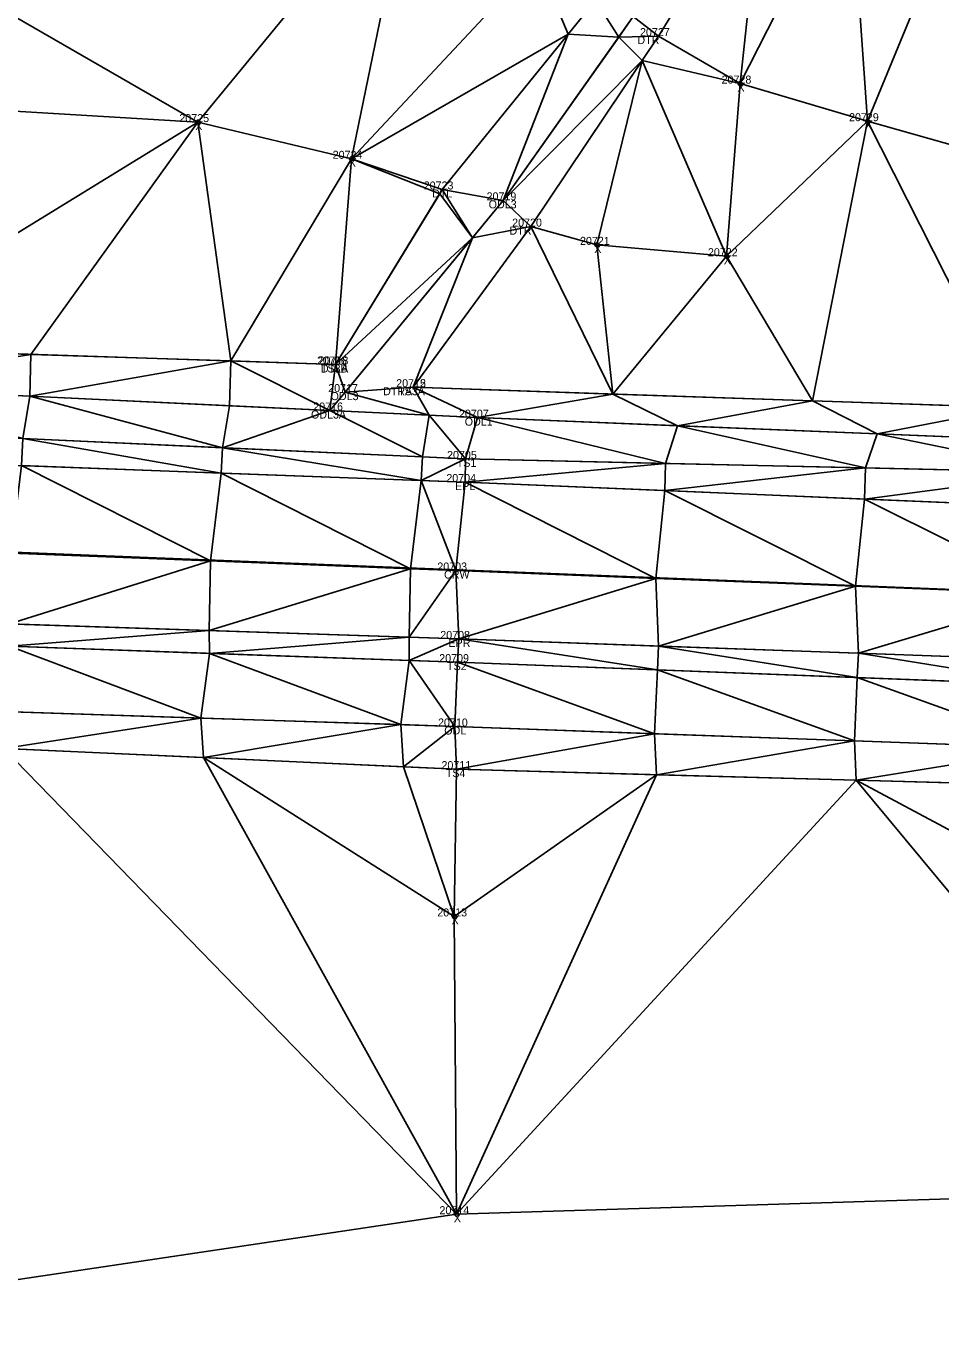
# Model space of a CAD drawing. Extents: x 1966740 to 1969291, y 1117379 to 1118460.
# Drawn here: x 1968833.8 to 1968948.1, y 1117803.8 to 1117968.4 of the extents above; entities that cross this region are included whole.
import ezdxf

# ---------------------------------------------------------------- set-up
doc = ezdxf.new("R2010")
doc.units = 0
for name, color, linetype in [('Level 1', 7, 'Continuous'), ('Level 10', 7, 'Continuous'), ('Level 3', 7, 'Continuous'), ('Level 30', 7, 'Continuous'), ('Level 35', 7, 'Continuous'), ('Level 50', 7, 'Continuous'), ('Level 52', 7, 'Continuous'), ('Level 53', 7, 'Continuous'), ('Level 56', 7, 'Continuous'), ('Level 6', 7, 'Continuous'), ('Level 60', 7, 'Continuous'), ('Level 61', 7, 'Continuous'), ('Level 62', 7, 'Continuous')]:
    doc.layers.add(name, color=color, linetype=linetype)

msp = doc.modelspace()

# ---------------------------------------------------------------- linework, layer by layer
at = {"layer": 'Level 1'}
msp.add_line((1968120.33, 1117930.94), (1969279.02, 1117884.95), dxfattribs=at)
at = {"layer": 'Level 10'}
for points in [[(1968872.44, 1117926.13), (1968885.78, 1117948), (1968904.93, 1117971.61), (1968923.41, 1117996.78), (1968940.56, 1118022.16)], [(1968882.13, 1117923.29), (1968896.84, 1117943.36), (1968912.83, 1117967.16), (1968928.85, 1117993.17), (1968947.1, 1118017.99)]]:
    msp.add_lwpolyline(points, dxfattribs=at)
at = {"layer": 'Level 3'}
for points in [[(1968532.27, 1117940.77), (1968682.68, 1117932.75), (1968784.38, 1117929.07), (1968872.44, 1117926.13)], [(1968531.49, 1117931.42), (1968682.06, 1117924.3), (1968783.42, 1117919.17), (1968888.7, 1117914.33), (1968991.06, 1117912.02), (1969093.07, 1117907.16), (1969191.83, 1117902.92), (1969283.72, 1117899.63)], [(1968530.54, 1117925.7), (1968681.97, 1117919.01), (1968783.23, 1117915.36), (1968888.64, 1117911.44), (1968991.22, 1117907.09), (1969091.98, 1117903.06), (1969191.09, 1117898.66), (1969283.27, 1117895.43)], [(1968882.13, 1117923.29), (1968991.72, 1117919.56), (1969094.35, 1117914.97), (1969192.08, 1117910.66), (1969282.99, 1117908.48)], [(1968529.36, 1117916.3), (1968681.48, 1117908.5), (1968781.89, 1117904.51), (1968887.49, 1117900.39), (1968989.06, 1117896.4), (1969090.87, 1117891.24), (1969190.23, 1117887.94), (1969284.4, 1117884.73)], [(1968527.82, 1117906.41), (1968680.79, 1117899.07), (1968781.71, 1117895.37), (1968887.86, 1117891.84), (1968988.65, 1117888.23), (1969090.1, 1117882.83), (1969189.3, 1117879.04), (1969282.94, 1117875.42)], [(1968528.99, 1117899.6), (1968680.45, 1117894.84), (1968781.74, 1117892.71), (1968887.7, 1117888.94), (1968987.81, 1117885.08), (1969089.75, 1117880.01), (1969189.02, 1117876.39), (1969282.76, 1117873.05)], [(1968528.68, 1117880.51), (1968680.3, 1117884.55), (1968781.05, 1117880.46), (1968887.57, 1117875.57), (1968986, 1117872.85), (1969087.95, 1117867.56), (1969189.32, 1117864.4), (1969289.73, 1117862.33)]]:
    msp.add_lwpolyline(points, dxfattribs=at)
at = {"layer": 'Level 30'}
for centre in [(1968923.03, 1117961.23), (1968855.24, 1117956.42), (1968938.93, 1117956.53), (1968874.43, 1117951.83), (1968905.11, 1117941.08), (1968921.32, 1117939.66), (1968887.28, 1117857.17), (1968887.56, 1117819.96)]:
    msp.add_circle(centre, 0.25, dxfattribs=at)
at = {"layer": 'Level 35'}
for points in [[(1968785.82, 1117960.59), (1968789.99, 1117994), (1968855.24, 1117956.42)], [(1968789.99, 1117994), (1968882.12, 1117989.12), (1968855.24, 1117956.42)], [(1968855.24, 1117956.42), (1968882.12, 1117989.12), (1968874.43, 1117951.83)], [(1968874.43, 1117951.83), (1968882.12, 1117989.12), (1968897.65, 1117976.64)], [(1968909.65, 1117969.6), (1968925.94, 1117988.45), (1968912.83, 1117967.16)], [(1968912.83, 1117967.16), (1968925.94, 1117988.45), (1968923.03, 1117961.23)], [(1968923.03, 1117961.23), (1968925.94, 1117988.45), (1968936.75, 1117988.2)], [(1968923.03, 1117961.23), (1968936.75, 1117988.2), (1968938.93, 1117956.53)], [(1968936.75, 1117988.2), (1968949.07, 1117981.12), (1968938.93, 1117956.53)], [(1968938.93, 1117956.53), (1968949.07, 1117981.12), (1968995.87, 1117940.46)], [(1968874.43, 1117951.83), (1968897.65, 1117976.64), (1968901.53, 1117967.41)], [(1968897.65, 1117976.64), (1968904.93, 1117971.61), (1968901.53, 1117967.41)], [(1968901.53, 1117967.41), (1968904.93, 1117971.61), (1968907.84, 1117967.04)], [(1968904.93, 1117971.61), (1968909.65, 1117969.6), (1968907.84, 1117967.04)], [(1968907.84, 1117967.04), (1968909.65, 1117969.6), (1968912.83, 1117967.16)], [(1968874.43, 1117951.83), (1968901.53, 1117967.41), (1968885.78, 1117948)], [(1968885.78, 1117948), (1968901.53, 1117967.41), (1968893.41, 1117946.64)], [(1968893.41, 1117946.64), (1968901.53, 1117967.41), (1968907.84, 1117967.04)], [(1968893.41, 1117946.64), (1968907.84, 1117967.04), (1968910.78, 1117964.12)], [(1968907.84, 1117967.04), (1968912.83, 1117967.16), (1968910.78, 1117964.12)], [(1968910.78, 1117964.12), (1968912.83, 1117967.16), (1968923.03, 1117961.23)], [(1968893.41, 1117946.64), (1968910.78, 1117964.12), (1968896.84, 1117943.36)], [(1968896.84, 1117943.36), (1968910.78, 1117964.12), (1968905.11, 1117941.08)], [(1968905.11, 1117941.08), (1968910.78, 1117964.12), (1968921.32, 1117939.66)], [(1968910.78, 1117964.12), (1968923.03, 1117961.23), (1968921.32, 1117939.66)], [(1968921.32, 1117939.66), (1968923.03, 1117961.23), (1968938.93, 1117956.53)], [(1968785.82, 1117960.59), (1968855.24, 1117956.42), (1968809.36, 1117928.24)], [(1968809.36, 1117928.24), (1968855.24, 1117956.42), (1968834.35, 1117927.4)], [(1968834.35, 1117927.4), (1968855.24, 1117956.42), (1968859.33, 1117926.57)], [(1968855.24, 1117956.42), (1968874.43, 1117951.83), (1968859.33, 1117926.57)], [(1968921.32, 1117939.66), (1968938.93, 1117956.53), (1968932.08, 1117921.59)], [(1968932.08, 1117921.59), (1968938.93, 1117956.53), (1968957.06, 1117920.74)], [(1968938.93, 1117956.53), (1968995.87, 1117940.46), (1968957.06, 1117920.74)], [(1968859.33, 1117926.57), (1968874.43, 1117951.83), (1968872.44, 1117926.13)], [(1968872.44, 1117926.13), (1968874.43, 1117951.83), (1968885.46, 1117947.47)], [(1968874.43, 1117951.83), (1968885.78, 1117948), (1968885.46, 1117947.47)], [(1968885.46, 1117947.47), (1968885.78, 1117948), (1968889.55, 1117941.97)], [(1968885.78, 1117948), (1968893.41, 1117946.64), (1968889.55, 1117941.97)], [(1968872.44, 1117926.13), (1968885.46, 1117947.47), (1968889.55, 1117941.97)], [(1968889.55, 1117941.97), (1968893.41, 1117946.64), (1968896.84, 1117943.36)], [(1968882.13, 1117923.29), (1968889.55, 1117941.97), (1968896.84, 1117943.36)], [(1968882.13, 1117923.29), (1968896.84, 1117943.36), (1968907.11, 1117922.44)], [(1968896.84, 1117943.36), (1968905.11, 1117941.08), (1968907.11, 1117922.44)], [(1968872.44, 1117926.13), (1968889.55, 1117941.97), (1968873.64, 1117922.68)], [(1968873.64, 1117922.68), (1968889.55, 1117941.97), (1968882.13, 1117923.29)], [(1968905.11, 1117941.08), (1968921.32, 1117939.66), (1968907.11, 1117922.44)], [(1968907.11, 1117922.44), (1968921.32, 1117939.66), (1968932.08, 1117921.59)], [(1968809.25, 1117923.37), (1968809.36, 1117928.24), (1968834.35, 1117927.4)], [(1968809.25, 1117923.37), (1968834.35, 1117927.4), (1968834.22, 1117922.17)], [(1968834.22, 1117922.17), (1968834.35, 1117927.4), (1968859.33, 1117926.57)], [(1968834.22, 1117922.17), (1968859.33, 1117926.57), (1968859.19, 1117920.98)], [(1968859.19, 1117920.98), (1968859.33, 1117926.57), (1968871.74, 1117920.38)], [(1968859.33, 1117926.57), (1968872.44, 1117926.13), (1968871.74, 1117920.38)], [(1968871.74, 1117920.38), (1968872.44, 1117926.13), (1968873.64, 1117922.68)], [(1968809.25, 1117923.37), (1968834.22, 1117922.17), (1968833.35, 1117916.87)], [(1968873.64, 1117922.68), (1968882.13, 1117923.29), (1968884.15, 1117919.78)], [(1968882.13, 1117923.29), (1968907.11, 1117922.44), (1968890.2, 1117919.49)], [(1968882.13, 1117923.29), (1968890.2, 1117919.49), (1968884.15, 1117919.78)], [(1968833.35, 1117916.87), (1968834.22, 1117922.17), (1968858.32, 1117915.73)], [(1968834.22, 1117922.17), (1968859.19, 1117920.98), (1968858.32, 1117915.73)], [(1968871.74, 1117920.38), (1968873.64, 1117922.68), (1968884.15, 1117919.78)], [(1968890.2, 1117919.49), (1968907.11, 1117922.44), (1968915.17, 1117918.47)], [(1968907.11, 1117922.44), (1968932.08, 1117921.59), (1968915.17, 1117918.47)], [(1968858.32, 1117915.73), (1968859.19, 1117920.98), (1968871.74, 1117920.38)], [(1968858.32, 1117915.73), (1968871.74, 1117920.38), (1968883.29, 1117914.58)], [(1968871.74, 1117920.38), (1968884.15, 1117919.78), (1968883.29, 1117914.58)], [(1968915.17, 1117918.47), (1968932.08, 1117921.59), (1968940.14, 1117917.45)], [(1968932.08, 1117921.59), (1968957.06, 1117920.74), (1968940.14, 1117917.45)], [(1968940.14, 1117917.45), (1968957.06, 1117920.74), (1968965.12, 1117916.43)], [(1968883.29, 1117914.58), (1968884.15, 1117919.78), (1968888.7, 1117914.33)], [(1968884.15, 1117919.78), (1968890.2, 1117919.49), (1968888.7, 1117914.33)], [(1968888.7, 1117914.33), (1968890.2, 1117919.49), (1968913.69, 1117913.76)], [(1968890.2, 1117919.49), (1968915.17, 1117918.47), (1968913.69, 1117913.76)], [(1968913.69, 1117913.76), (1968915.17, 1117918.47), (1968938.68, 1117913.2)], [(1968915.17, 1117918.47), (1968940.14, 1117917.45), (1968938.68, 1117913.2)], [(1968833.18, 1117913.5), (1968833.35, 1117916.87), (1968858.16, 1117912.57)], [(1968833.35, 1117916.87), (1968858.32, 1117915.73), (1968858.16, 1117912.57)], [(1968938.68, 1117913.2), (1968940.14, 1117917.45), (1968963.67, 1117912.63)], [(1968940.14, 1117917.45), (1968965.12, 1117916.43), (1968963.67, 1117912.63)], [(1968858.16, 1117912.57), (1968858.32, 1117915.73), (1968883.14, 1117911.64)], [(1968858.32, 1117915.73), (1968883.29, 1117914.58), (1968883.14, 1117911.64)], [(1968831.84, 1117902.56), (1968833.18, 1117913.5), (1968856.81, 1117901.58)], [(1968833.18, 1117913.5), (1968858.16, 1117912.57), (1968856.81, 1117901.58)], [(1968883.14, 1117911.64), (1968883.29, 1117914.58), (1968888.7, 1117914.33)], [(1968883.14, 1117911.64), (1968888.7, 1117914.33), (1968888.64, 1117911.44)], [(1968888.64, 1117911.44), (1968888.7, 1117914.33), (1968913.69, 1117913.76)], [(1968888.64, 1117911.44), (1968913.69, 1117913.76), (1968913.61, 1117910.38)], [(1968913.61, 1117910.38), (1968913.69, 1117913.76), (1968938.68, 1117913.2)], [(1968856.81, 1117901.58), (1968858.16, 1117912.57), (1968881.79, 1117900.61)], [(1968858.16, 1117912.57), (1968883.14, 1117911.64), (1968881.79, 1117900.61)], [(1968913.61, 1117910.38), (1968938.68, 1117913.2), (1968938.58, 1117909.32)], [(1968938.58, 1117909.32), (1968938.68, 1117913.2), (1968963.67, 1117912.63)], [(1968938.58, 1117909.32), (1968963.67, 1117912.63), (1968963.55, 1117908.26)], [(1968881.79, 1117900.61), (1968883.14, 1117911.64), (1968887.49, 1117900.39)], [(1968883.14, 1117911.64), (1968888.64, 1117911.44), (1968887.49, 1117900.39)], [(1968887.49, 1117900.39), (1968888.64, 1117911.44), (1968912.46, 1117899.41)], [(1968888.64, 1117911.44), (1968913.61, 1117910.38), (1968912.46, 1117899.41)], [(1968912.46, 1117899.41), (1968913.61, 1117910.38), (1968937.44, 1117898.43)], [(1968913.61, 1117910.38), (1968938.58, 1117909.32), (1968937.44, 1117898.43)], [(1968937.44, 1117898.43), (1968938.58, 1117909.32), (1968962.41, 1117897.45)], [(1968938.58, 1117909.32), (1968963.55, 1117908.26), (1968962.41, 1117897.45)], [(1968831.67, 1117893.71), (1968831.84, 1117902.56), (1968856.81, 1117901.58)], [(1968831.67, 1117893.71), (1968856.81, 1117901.58), (1968856.65, 1117892.88)], [(1968856.65, 1117892.88), (1968856.81, 1117901.58), (1968881.79, 1117900.61)], [(1968856.65, 1117892.88), (1968881.79, 1117900.61), (1968881.64, 1117892.05)], [(1968881.64, 1117892.05), (1968881.79, 1117900.61), (1968887.49, 1117900.39)], [(1968881.64, 1117892.05), (1968887.49, 1117900.39), (1968887.86, 1117891.84)], [(1968887.49, 1117900.39), (1968912.46, 1117899.41), (1968887.86, 1117891.84)], [(1968887.86, 1117891.84), (1968912.46, 1117899.41), (1968912.83, 1117890.95)], [(1968912.46, 1117899.41), (1968937.44, 1117898.43), (1968912.83, 1117890.95)], [(1968912.83, 1117890.95), (1968937.44, 1117898.43), (1968937.81, 1117890.05)], [(1968937.44, 1117898.43), (1968962.41, 1117897.45), (1968937.81, 1117890.05)], [(1968937.81, 1117890.05), (1968962.41, 1117897.45), (1968962.79, 1117889.16)], [(1968831.67, 1117893.71), (1968856.65, 1117892.88), (1968831.7, 1117890.93)], [(1968831.7, 1117890.93), (1968856.65, 1117892.88), (1968856.68, 1117890.04)], [(1968856.65, 1117892.88), (1968881.64, 1117892.05), (1968856.68, 1117890.04)], [(1968856.68, 1117890.04), (1968881.64, 1117892.05), (1968881.66, 1117889.15)], [(1968881.64, 1117892.05), (1968887.86, 1117891.84), (1968881.66, 1117889.15)], [(1968830.63, 1117882.79), (1968831.7, 1117890.93), (1968855.61, 1117881.96)], [(1968831.7, 1117890.93), (1968856.68, 1117890.04), (1968855.61, 1117881.96)], [(1968881.66, 1117889.15), (1968887.86, 1117891.84), (1968887.7, 1117888.94)], [(1968887.7, 1117888.94), (1968887.86, 1117891.84), (1968912.68, 1117887.98)], [(1968887.86, 1117891.84), (1968912.83, 1117890.95), (1968912.68, 1117887.98)], [(1968912.68, 1117887.98), (1968912.83, 1117890.95), (1968937.65, 1117887.01)], [(1968912.83, 1117890.95), (1968937.81, 1117890.05), (1968937.65, 1117887.01)], [(1968855.61, 1117881.96), (1968856.68, 1117890.04), (1968880.59, 1117881.13)], [(1968856.68, 1117890.04), (1968881.66, 1117889.15), (1968880.59, 1117881.13)], [(1968880.59, 1117881.13), (1968881.66, 1117889.15), (1968887.36, 1117880.9)], [(1968881.66, 1117889.15), (1968887.7, 1117888.94), (1968887.36, 1117880.9)], [(1968887.36, 1117880.9), (1968887.7, 1117888.94), (1968912.33, 1117880)], [(1968887.7, 1117888.94), (1968912.68, 1117887.98), (1968912.33, 1117880)], [(1968937.65, 1117887.01), (1968937.81, 1117890.05), (1968962.63, 1117886.05)], [(1968937.81, 1117890.05), (1968962.79, 1117889.16), (1968962.63, 1117886.05)], [(1968912.33, 1117880), (1968912.68, 1117887.98), (1968937.31, 1117879.1)], [(1968912.68, 1117887.98), (1968937.65, 1117887.01), (1968937.31, 1117879.1)], [(1968937.31, 1117879.1), (1968937.65, 1117887.01), (1968962.29, 1117878.2)], [(1968937.65, 1117887.01), (1968962.63, 1117886.05), (1968962.29, 1117878.2)], [(1968830.63, 1117882.79), (1968855.61, 1117881.96), (1968830.98, 1117878.17)], [(1968830.98, 1117878.17), (1968855.61, 1117881.96), (1968855.95, 1117877.02)], [(1968855.61, 1117881.96), (1968880.59, 1117881.13), (1968855.95, 1117877.02)], [(1968855.95, 1117877.02), (1968880.59, 1117881.13), (1968880.92, 1117875.87)], [(1968880.59, 1117881.13), (1968887.36, 1117880.9), (1968880.92, 1117875.87)], [(1968880.92, 1117875.87), (1968887.36, 1117880.9), (1968887.57, 1117875.57)], [(1968887.36, 1117880.9), (1968912.33, 1117880), (1968887.57, 1117875.57)], [(1968887.57, 1117875.57), (1968912.33, 1117880), (1968912.56, 1117874.88)], [(1968912.33, 1117880), (1968937.31, 1117879.1), (1968912.56, 1117874.88)], [(1968912.56, 1117874.88), (1968937.31, 1117879.1), (1968937.54, 1117874.19)], [(1968937.31, 1117879.1), (1968962.29, 1117878.2), (1968937.54, 1117874.19)], [(1968779.05, 1117803.79), (1968830.98, 1117878.17), (1968887.56, 1117819.96)], [(1968830.98, 1117878.17), (1968855.95, 1117877.02), (1968887.56, 1117819.96)], [(1968937.54, 1117874.19), (1968962.29, 1117878.2), (1968962.52, 1117873.5)], [(1968855.95, 1117877.02), (1968880.92, 1117875.87), (1968887.28, 1117857.17)], [(1968855.95, 1117877.02), (1968887.28, 1117857.17), (1968887.56, 1117819.96)], [(1968880.92, 1117875.87), (1968887.57, 1117875.57), (1968887.28, 1117857.17)], [(1968887.28, 1117857.17), (1968887.57, 1117875.57), (1968912.56, 1117874.88)], [(1968887.28, 1117857.17), (1968912.56, 1117874.88), (1968887.56, 1117819.96)], [(1968887.56, 1117819.96), (1968912.56, 1117874.88), (1968937.54, 1117874.19)], [(1968887.56, 1117819.96), (1968937.54, 1117874.19), (1968980.18, 1117822.86)], [(1968937.54, 1117874.19), (1968962.52, 1117873.5), (1968980.57, 1117851.21)], [(1968937.54, 1117874.19), (1968980.57, 1117851.21), (1968980.18, 1117822.86)]]:
    msp.add_lwpolyline(points, close=True, dxfattribs=at)
at = {"layer": 'Level 50'}
for centre in [(1968912.83, 1117967.16), (1968885.78, 1117948), (1968893.41, 1117946.64), (1968896.84, 1117943.36), (1968872.44, 1117926.13), (1968872.44, 1117926.13), (1968882.13, 1117923.29), (1968882.13, 1117923.29), (1968873.64, 1117922.68), (1968871.74, 1117920.38), (1968890.2, 1117919.49), (1968888.7, 1117914.33), (1968888.64, 1117911.44), (1968887.49, 1117900.39), (1968887.86, 1117891.84), (1968887.7, 1117888.94), (1968887.36, 1117880.9), (1968887.57, 1117875.57)]:
    msp.add_circle(centre, 0.001, dxfattribs=at)
at = {"layer": 'Level 6'}
for points in [[(1968871.74, 1117920.38), (1968873.64, 1117922.68), (1968893.41, 1117946.64), (1968909.65, 1117969.6), (1968926.07, 1117994.82), (1968943.8, 1118019.85)], [(1968531.76, 1117937.18), (1968682.22, 1117928.11), (1968784.28, 1117924.56), (1968890.2, 1117919.49), (1968991.22, 1117915.37), (1969093.76, 1117910.9), (1969192.08, 1117906.24), (1969283.24, 1117903.06)], [(1968528.55, 1117888.35), (1968679.78, 1117887.39), (1968780.67, 1117884.45), (1968887.36, 1117880.9), (1968987.02, 1117877.31), (1969088.58, 1117870.53), (1969189.53, 1117868.6), (1969284.94, 1117865.64)]]:
    msp.add_lwpolyline(points, dxfattribs=at)

# ---------------------------------------------------------------- texts
at = {"layer": 'Level 52'}
for s, p in [('20728', (1968920.7, 1117961.23)), ('20725', (1968852.91, 1117956.42)), ('20729', (1968936.63, 1117956.53)), ('20724', (1968872.08, 1117951.83)), ('ODL3', (1968891.58, 1117945.64)), ('20721', (1968903, 1117941.08)), ('20722', (1968918.99, 1117939.66)), ('ODL3', (1968871.82, 1117921.68)), ('ODL3A', (1968869.37, 1117919.38)), ('20713', (1968885.16, 1117857.17)), ('20714', (1968885.43, 1117819.96))]:
    msp.add_text(s, height=1, dxfattribs=at).set_placement(p)
at = {"layer": 'Level 53'}
for s, p in [('20719', (1968891.32, 1117946.64)), ('20706', (1968870.13, 1117926.13)), ('TS3B', (1968870.61, 1117925.13)), ('20717', (1968871.52, 1117922.68)), ('20712', (1968880.02, 1117923.29)), ('TS3A', (1968880.26, 1117922.29)), ('20716', (1968869.65, 1117920.38)), ('20707', (1968887.87, 1117919.49)), ('ODL1', (1968888.59, 1117918.49)), ('20705', (1968886.38, 1117914.33)), ('TS1', (1968887.59, 1117913.33)), ('20704', (1968886.29, 1117911.44)), ('EPL', (1968887.38, 1117910.44)), ('20703', (1968885.16, 1117900.39)), ('CRW', (1968886, 1117899.39)), ('20708', (1968885.53, 1117891.84)), ('EPR', (1968886.55, 1117890.84)), ('20709', (1968885.4, 1117888.94)), ('TS2', (1968886.38, 1117887.94)), ('20711', (1968885.68, 1117875.57)), ('TS4', (1968886.22, 1117874.57))]:
    msp.add_text(s, height=1, dxfattribs=at).set_placement(p)
at = {"layer": 'Level 56'}
for s, p in [('20710', (1968885.25, 1117880.9)), ('ODL', (1968886.03, 1117879.9))]:
    msp.add_text(s, height=1, dxfattribs=at).set_placement(p)
at = {"layer": 'Level 60'}
for s, p in [('DTR', (1968910.17, 1117966.16)), ('DTL', (1968884.5, 1117947)), ('DTR', (1968894.19, 1117942.36)), ('DTLA', (1968870.61, 1117925.13)), ('DTRA', (1968878.38, 1117922.29))]:
    msp.add_text(s, height=1, dxfattribs=at).set_placement(p)
at = {"layer": 'Level 61'}
for s, p in [('20727', (1968910.5, 1117967.16)), ('20723', (1968883.46, 1117948)), ('20720', (1968894.52, 1117943.36)), ('20718', (1968870.32, 1117926.13)), ('20715', (1968880.02, 1117923.29))]:
    msp.add_text(s, height=1, dxfattribs=at).set_placement(p)
at = {"layer": 'Level 62'}
for p in [(1968922.69, 1117960.23), (1968854.9, 1117955.42), (1968938.6, 1117955.53), (1968874.1, 1117950.83), (1968904.78, 1117940.08), (1968920.98, 1117938.66), (1968886.94, 1117856.17), (1968887.23, 1117818.96)]:
    msp.add_text('X', height=1, dxfattribs=at).set_placement(p)

doc.saveas('drawing.dxf')
